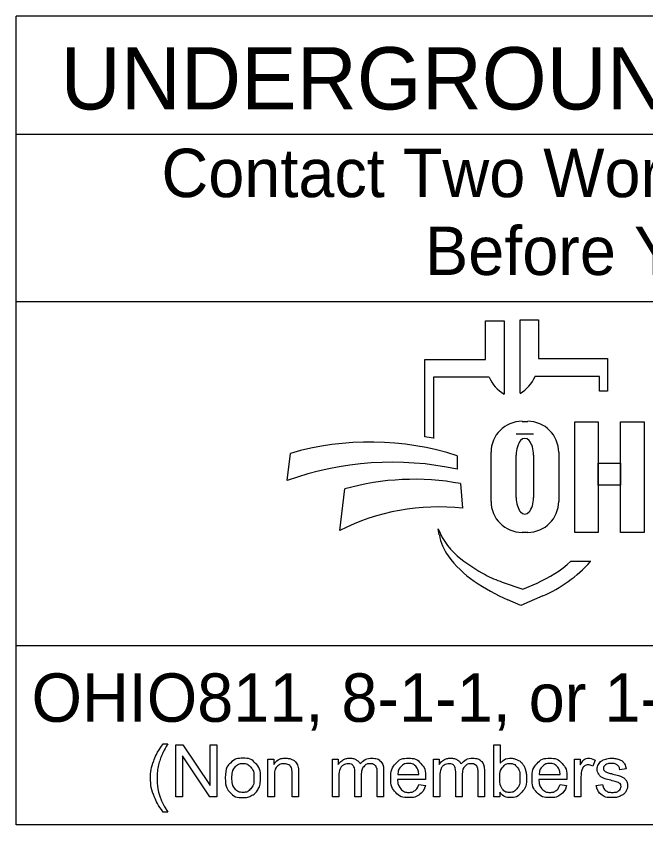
# Model space of a CAD drawing. Extents: x 0 to 34, y -1.2 to 22.
# Drawn here: x 6.375 to 8.193, y 2.14 to 4.478 of the extents above; entities that cross this region are included whole.
import ezdxf

# ---------------------------------------------------------------- set-up
doc = ezdxf.new("R2010")
doc.units = 0
doc.layers.add('SH_Cut_Line', color=7, linetype='Continuous')
doc.layers.add('SH_Data', color=7, linetype='Continuous')

msp = doc.modelspace()

# ---------------------------------------------------------------- linework, layer by layer
at = {"layer": 'SH_Cut_Line'}
for p, q in [((7.7307, 3.4855), (7.7307, 3.597)), ((7.7307, 3.597), (7.7843, 3.597)), ((7.7843, 3.597), (7.7843, 3.3849)), ((7.83, 3.3873), (7.83, 3.5993)), ((7.83, 3.5993), (7.8836, 3.5993)), ((7.8836, 3.5993), (7.8836, 3.4879)), ((7.5547, 3.2616), (7.5547, 3.4855)), ((7.5547, 3.4855), (7.7307, 3.4855)), ((7.8836, 3.4879), (8.0829, 3.4879)), ((8.0829, 3.4879), (8.0829, 3.394)), ((8.0596, 3.4364), (7.8732, 3.4364)), ((8.0596, 3.394), (8.0596, 3.4364)), ((7.58, 3.4341), (7.58, 3.2572)), ((7.7411, 3.4341), (7.58, 3.4341)), ((8.0829, 3.394), (8.0596, 3.394)), ((7.8357, 3.3063), (7.8522, 3.3063)), ((7.8689, 3.2693), (7.8191, 3.2693)), ((7.1574, 3.1353), (7.1667, 3.2135)), ((7.648, 3.207), (7.648, 3.1681)), ((7.7462, 3.0749), (7.7462, 3.2169)), ((7.8191, 3.0863), (7.8191, 3.2086)), ((7.8689, 3.2086), (7.8689, 3.0863)), ((7.9417, 3.2169), (7.9417, 3.0749)), ((7.3092, 2.9908), (7.3239, 3.1109)), ((7.658, 3.1264), (7.6642, 3.0554)), ((7.5969, 2.9779), (7.5938, 2.9958)), ((7.8522, 2.9854), (7.8357, 2.9854)), ((7.9772, 2.902), (8.0346, 2.902)), ((7.7787, 2.8416), (7.8382, 2.8212)), ((7.8382, 2.8212), (7.8792, 2.839)), ((7.8321, 2.7741), (7.7948, 2.7906)), ((7.8954, 2.8016), (7.8321, 2.7741))]:
    msp.add_line(p, q, dxfattribs=at)
for points in [[(7.9881, 3.3053), (8.0561, 3.3053), (8.0561, 2.9853), (7.9881, 2.9853)], [(8.1203, 3.3053), (8.1882, 3.3053), (8.1882, 2.9853), (8.1203, 2.9853)], [(8.0561, 3.1854), (8.1203, 3.1854), (8.1203, 3.1214), (8.0561, 3.1214)]]:
    msp.add_lwpolyline(points, close=True, dxfattribs=at)
for points in [[(6.7993, 2.3738), (6.8124, 2.3738)], [(6.836, 2.2212), (6.836, 2.3713), (6.8563, 2.3713), (6.9353, 2.2534), (6.9353, 2.3713), (6.9543, 2.3713), (6.9543, 2.2212), (6.934, 2.2212), (6.855, 2.3391), (6.855, 2.2212), (6.836, 2.2212)], [(7.7715, 2.2212), (7.7544, 2.2212), (7.7544, 2.3713), (7.7728, 2.3713), (7.7728, 2.3178)], [(7.102, 2.2212), (7.102, 2.33), (7.1186, 2.33), (7.1186, 2.3145)], [(7.2884, 2.2212), (7.2884, 2.33), (7.3049, 2.33), (7.3049, 2.3146)], [(7.5798, 2.2212), (7.5798, 2.33), (7.5962, 2.33), (7.5962, 2.3146)], [(7.9875, 2.2212), (7.9875, 2.33), (8.0041, 2.33), (8.0041, 2.3135)], [(8.0466, 2.3265), (8.0401, 2.3094)], [(7.3715, 2.2843), (7.3715, 2.2212), (7.353, 2.2212), (7.353, 2.2918)], [(7.4359, 2.2958), (7.4359, 2.2212), (7.4175, 2.2212), (7.4175, 2.2896)], [(7.6628, 2.2843), (7.6628, 2.2212), (7.6444, 2.2212), (7.6444, 2.2918)], [(7.7273, 2.2958), (7.7273, 2.2212), (7.7089, 2.2212), (7.7089, 2.2896)], [(8.1365, 2.3018), (8.1185, 2.2994)], [(7.1204, 2.2805), (7.1204, 2.2212), (7.102, 2.2212)], [(7.1903, 2.288), (7.1903, 2.2212), (7.1719, 2.2212), (7.1719, 2.2873)], [(7.3068, 2.2776), (7.3068, 2.2212), (7.2884, 2.2212)], [(7.5571, 2.2708), (7.476, 2.2708)], [(7.477, 2.2859), (7.5378, 2.2859)], [(7.5982, 2.2776), (7.5982, 2.2212), (7.5798, 2.2212)], [(7.9651, 2.2708), (7.884, 2.2708)], [(7.885, 2.2859), (7.9458, 2.2859)], [(8.006, 2.2781), (8.006, 2.2212), (7.9875, 2.2212)], [(7.5376, 2.2563), (7.5566, 2.2539)], [(7.9456, 2.2563), (7.9646, 2.2539)], [(8.0501, 2.2537), (8.0683, 2.2565)], [(7.7715, 2.2348), (7.7715, 2.2212)], [(6.8124, 2.177), (6.7993, 2.177)]]:
    msp.add_lwpolyline(points, dxfattribs=at)
for centre, radius, start, end in [((7.7819, 3.4732), 0.0985, 299.2531, 338.0704), ((7.8324, 3.4709), 0.0985, 201.9296, 240.7469), ((7.8357, 3.2169), 0.0895, 90, 180), ((7.8522, 3.2169), 0.0895, 0, 90), ((7.4266, 2.4527), 0.8191, 79.2074, 81.0007), ((7.3968, 2.4274), 0.8191, 72.1402, 106.3144), ((7.4599, 2.2963), 0.8919, 77.8238, 109.8274), ((7.5238, 2.4066), 0.7322, 79.44, 105.8467), ((7.8357, 3.0749), 0.0895, 180, 270), ((7.8522, 3.0749), 0.0895, 270, 0), ((7.5958, 2.4234), 0.6357, 83.8248, 116.8021), ((7.7812, 3.0679), 0.2008, 201.0457, 232.5314), ((7.7382, 3.002), 0.1433, 189.6817, 216.0884), ((7.8718, 3.0994), 0.3088, 216.0884, 235.7167), ((7.9738, 3.3191), 0.5173, 232.5314, 241.794), ((7.7358, 3.1694), 0.3602, 293.4582, 312.0712), ((7.7358, 3.1694), 0.401, 293.4582, 317.8286), ((7.8886, 3.1603), 0.3371, 241.794, 250.9821), ((8.0384, 3.3437), 0.6044, 235.7167, 246.2325)]:
    msp.add_arc(centre, radius, start, end, dxfattribs=at)
for centre, start_param, end_param in [((7.844, 3.2086), 4.712389, 7.853982), ((7.844, 3.0863), 1.570796, 4.712389)]:
    msp.add_ellipse(centre, major_axis=(0, 0.0484), ratio=0.514403, start_param=start_param, end_param=end_param, dxfattribs=at)
for points in [[(6.7993, 2.177), (6.784, 2.1962), (6.7734, 2.222), (6.7629, 2.2478), (6.7629, 2.2755), (6.7629, 2.2999), (6.7708, 2.3222), (6.78, 2.3481), (6.7993, 2.3738)], [(6.8124, 2.3738), (6.8001, 2.3525), (6.7961, 2.3434), (6.7898, 2.3293), (6.7863, 2.3139), (6.7819, 2.2948), (6.7819, 2.2754), (6.7819, 2.2261), (6.8124, 2.177)], [(6.9785, 2.2756), (6.9785, 2.3058), (6.9953, 2.3203), (7.0093, 2.3324), (7.0295, 2.3324), (7.0519, 2.3324), (7.0661, 2.3177), (7.0803, 2.303), (7.0803, 2.2771), (7.0803, 2.2561), (7.0741, 2.2441), (7.0678, 2.2321), (7.0557, 2.2254), (7.0437, 2.2187), (7.0295, 2.2187), (7.0066, 2.2187), (6.9926, 2.2334), (6.9785, 2.248), (6.9785, 2.2756)], [(6.9975, 2.2756), (6.9975, 2.2547), (7.0066, 2.2443), (7.0157, 2.2339), (7.0295, 2.2339), (7.0432, 2.2339), (7.0523, 2.2443), (7.0613, 2.2548), (7.0613, 2.2762), (7.0613, 2.2964), (7.0522, 2.3068), (7.0431, 2.3172), (7.0295, 2.3172), (7.0157, 2.3172), (7.0066, 2.3068), (6.9975, 2.2965), (6.9975, 2.2756)], [(7.1186, 2.3145), (7.1305, 2.3324), (7.1532, 2.3324), (7.163, 2.3324), (7.1712, 2.3289), (7.1795, 2.3253), (7.1836, 2.3196), (7.1877, 2.3139), (7.1893, 2.306), (7.1903, 2.3008), (7.1903, 2.288)], [(7.1719, 2.2873), (7.1719, 2.2986), (7.1698, 2.3041), (7.1676, 2.3097), (7.1621, 2.313), (7.1566, 2.3164), (7.1493, 2.3164), (7.1375, 2.3164), (7.129, 2.3089), (7.1204, 2.3014), (7.1204, 2.2805)], [(7.3049, 2.3146), (7.31, 2.3226), (7.3185, 2.3275), (7.327, 2.3324), (7.3379, 2.3324), (7.35, 2.3324), (7.3577, 2.3274), (7.3654, 2.3223), (7.3686, 2.3133), (7.3815, 2.3324), (7.4023, 2.3324), (7.4185, 2.3324), (7.4272, 2.3234), (7.4359, 2.3145), (7.4359, 2.2958)], [(7.353, 2.2918), (7.353, 2.3041), (7.3485, 2.3102), (7.344, 2.3164), (7.3338, 2.3164), (7.326, 2.3164), (7.3194, 2.3123), (7.3128, 2.3082), (7.3098, 2.3003), (7.3068, 2.2924), (7.3068, 2.2776)], [(7.4175, 2.2896), (7.4175, 2.3007), (7.4157, 2.3056), (7.4139, 2.3104), (7.4092, 2.3134), (7.4045, 2.3164), (7.3981, 2.3164), (7.3866, 2.3164), (7.3791, 2.3087), (7.3715, 2.3011), (7.3715, 2.2843)], [(7.5566, 2.2539), (7.5521, 2.2372), (7.5399, 2.228), (7.5277, 2.2187), (7.5088, 2.2187), (7.4849, 2.2187), (7.471, 2.2334), (7.457, 2.2481), (7.457, 2.2746), (7.457, 2.3021), (7.4711, 2.3172), (7.4852, 2.3324), (7.5078, 2.3324), (7.5296, 2.3324), (7.5434, 2.3175), (7.5572, 2.3027), (7.5572, 2.2757), (7.5572, 2.2741), (7.5571, 2.2708)], [(7.5378, 2.2859), (7.5365, 2.2997), (7.5308, 2.3066), (7.522, 2.3173), (7.508, 2.3173), (7.4952, 2.3173), (7.4866, 2.3088), (7.4779, 2.3002), (7.477, 2.2859)], [(7.5962, 2.3146), (7.6014, 2.3226), (7.6099, 2.3275), (7.6184, 2.3324), (7.6292, 2.3324), (7.6413, 2.3324), (7.6491, 2.3274), (7.6568, 2.3223), (7.66, 2.3133), (7.6729, 2.3324), (7.6936, 2.3324), (7.7098, 2.3324), (7.7186, 2.3234), (7.7273, 2.3145), (7.7273, 2.2958)], [(7.6444, 2.2918), (7.6444, 2.3041), (7.6399, 2.3102), (7.6354, 2.3164), (7.6251, 2.3164), (7.6174, 2.3164), (7.6107, 2.3123), (7.6041, 2.3082), (7.6012, 2.3003), (7.5982, 2.2924), (7.5982, 2.2776)], [(7.7089, 2.2896), (7.7089, 2.3007), (7.7071, 2.3056), (7.7053, 2.3104), (7.7006, 2.3134), (7.6958, 2.3164), (7.6895, 2.3164), (7.678, 2.3164), (7.6704, 2.3087), (7.6628, 2.3011), (7.6628, 2.2843)], [(7.7712, 2.2764), (7.7712, 2.2568), (7.7766, 2.2481), (7.7852, 2.2339), (7.8001, 2.2339), (7.8121, 2.2339), (7.8209, 2.2444), (7.8297, 2.2549), (7.8297, 2.2757), (7.8297, 2.297), (7.8213, 2.3071), (7.8129, 2.3173), (7.8009, 2.3173), (7.7888, 2.3173), (7.78, 2.3068), (7.7712, 2.2963), (7.7712, 2.2764)], [(7.7728, 2.3178), (7.7845, 2.3324), (7.8026, 2.3324), (7.8127, 2.3324), (7.8216, 2.3283), (7.8306, 2.3243), (7.8364, 2.317), (7.8422, 2.3097), (7.8454, 2.2993), (7.8487, 2.289), (7.8487, 2.2772), (7.8487, 2.2493), (7.8349, 2.234), (7.8211, 2.2187), (7.8017, 2.2187), (7.7824, 2.2187), (7.7715, 2.2348)], [(7.9646, 2.2539), (7.9601, 2.2372), (7.9479, 2.228), (7.9357, 2.2187), (7.9168, 2.2187), (7.8929, 2.2187), (7.8789, 2.2334), (7.865, 2.2481), (7.865, 2.2746), (7.865, 2.3021), (7.8791, 2.3172), (7.8932, 2.3324), (7.9158, 2.3324), (7.9376, 2.3324), (7.9514, 2.3175), (7.9652, 2.3027), (7.9652, 2.2757), (7.9652, 2.2741), (7.9651, 2.2708)], [(7.9458, 2.2859), (7.9445, 2.2997), (7.9388, 2.3066), (7.93, 2.3173), (7.9159, 2.3173), (7.9032, 2.3173), (7.8946, 2.3088), (7.8859, 2.3002), (7.885, 2.2859)], [(8.0041, 2.3135), (8.0105, 2.325), (8.0158, 2.3287), (8.0212, 2.3324), (8.0277, 2.3324), (8.037, 2.3324), (8.0466, 2.3265)], [(8.1185, 2.2994), (8.1172, 2.3078), (8.1113, 2.3126), (8.1054, 2.3173), (8.0947, 2.3173), (8.082, 2.3173), (8.0765, 2.3131), (8.0711, 2.3089), (8.0711, 2.3032), (8.0711, 2.2996), (8.0733, 2.2968), (8.0756, 2.2938), (8.0804, 2.2918), (8.0832, 2.2908), (8.0967, 2.2871), (8.1163, 2.2819), (8.1241, 2.2786), (8.1318, 2.2752), (8.1362, 2.2689), (8.1407, 2.2626), (8.1407, 2.2531), (8.1407, 2.2439), (8.1353, 2.2358), (8.1299, 2.2277), (8.1197, 2.2232), (8.1096, 2.2187), (8.0967, 2.2187), (8.0755, 2.2187), (8.0644, 2.2276), (8.0532, 2.2364), (8.0501, 2.2537)], [(8.0683, 2.2565), (8.0699, 2.2455), (8.0769, 2.2397), (8.084, 2.2339), (8.0966, 2.2339), (8.1093, 2.2339), (8.1155, 2.239), (8.1217, 2.2442), (8.1217, 2.2512), (8.1217, 2.2575), (8.1162, 2.261), (8.1124, 2.2635), (8.0973, 2.2673), (8.077, 2.2724), (8.0692, 2.2762), (8.0613, 2.2799), (8.0573, 2.2865), (8.0532, 2.2931), (8.0532, 2.3011), (8.0532, 2.3083), (8.0566, 2.3145), (8.0599, 2.3207), (8.0656, 2.3248), (8.07, 2.328), (8.0774, 2.3302), (8.0848, 2.3324), (8.0933, 2.3324), (8.1062, 2.3324), (8.1159, 2.3287), (8.1256, 2.325), (8.1302, 2.3187), (8.1348, 2.3124), (8.1365, 2.3018)], [(8.0401, 2.3094), (8.0334, 2.3134), (8.0267, 2.3134), (8.0207, 2.3134), (8.0159, 2.3098), (8.0111, 2.3061), (8.009, 2.2997), (8.006, 2.2898), (8.006, 2.2781)], [(7.476, 2.2708), (7.477, 2.2529), (7.4861, 2.2434), (7.4952, 2.2339), (7.5089, 2.2339), (7.519, 2.2339), (7.5262, 2.2392), (7.5334, 2.2446), (7.5376, 2.2563)], [(7.884, 2.2708), (7.885, 2.2529), (7.8941, 2.2434), (7.9032, 2.2339), (7.9169, 2.2339), (7.927, 2.2339), (7.9342, 2.2392), (7.9414, 2.2446), (7.9456, 2.2563)]]:
    msp.add_open_spline(points, degree=3, dxfattribs=at)
at = {"layer": 'SH_Data'}
for p, q in [((6.3747, 2.14), (6.3747, 4.4775)), ((10.6247, 4.4775), (6.3747, 4.4775)), ((6.3747, 4.136), (10.6247, 4.136)), ((6.3747, 3.6526), (10.6247, 3.6526)), ((10.6247, 2.6579), (6.3747, 2.6579)), ((10.6247, 2.14), (6.3747, 2.14))]:
    msp.add_line(p, q, dxfattribs=at)

# ---------------------------------------------------------------- texts
at = {"layer": 'SH_Cut_Line'}
for s, height, p in [('UNDERGROUND UTILITIES', 0.18, (6.5028, 4.2079)), ('Contact Two Working Days', 0.14, (6.7943, 3.9544)), ('Before You Dig', 0.14, (7.5555, 3.7294)), ('OHIO811, 8-1-1, or 1-800-362-2764', 0.14, (6.4191, 2.4378))]:
    msp.add_text(s, height=height, dxfattribs=at).set_placement(p)

doc.saveas('drawing.dxf')
